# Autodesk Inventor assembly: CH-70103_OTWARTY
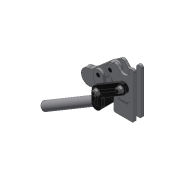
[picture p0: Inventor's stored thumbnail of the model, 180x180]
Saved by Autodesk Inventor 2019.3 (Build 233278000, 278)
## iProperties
Company: Î¢ÈíÖÐ¹ú
Created: 2012-10
Part Number: CH-70103_OTWARTY
Material: Ogólny
Description: STEP AP203
Document SubType Name: Assembly
Designer: CADENGINEERING4
Stock Number: DOCISKI CIĘŻKIE
Sending System: SolidWorks 2010
Preprocessor: SwSTEP 2.0
Title: CH-70103.STEP
Author: Î¢ÈíÓÃ»§
Revision Number: ÈÎºÎ
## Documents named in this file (11)
- D:\Vault_2016\Projekty\NASZ KATALOG\CLAMPTEK\STRONA\Heavy duty weldables\CH-70103\CH-70103_OTWARTY.iam
- D:\Vault_2016\Projekty\NASZ KATALOG\CLAMPTEK\STRONA\Heavy duty weldables\CH-70103\3-8-16 LOCK NUT.ipt
- D:\Vault_2016\Projekty\NASZ KATALOG\CLAMPTEK\STRONA\Heavy duty weldables\CH-70103\70103-10.ipt
- D:\Vault_2016\Projekty\NASZ KATALOG\CLAMPTEK\STRONA\Heavy duty weldables\CH-70103\70103-06.ipt
- D:\Vault_2016\Projekty\NASZ KATALOG\CLAMPTEK\STRONA\Heavy duty weldables\CH-70103\70103-04.ipt
- D:\Vault_2016\Projekty\NASZ KATALOG\CLAMPTEK\STRONA\Heavy duty weldables\CH-70103\70103-08.ipt
- D:\Vault_2016\Projekty\NASZ KATALOG\CLAMPTEK\STRONA\Heavy duty weldables\CH-70103\70103-02.ipt
- D:\Vault_2016\Projekty\NASZ KATALOG\CLAMPTEK\STRONA\Heavy duty weldables\CH-70103\70103-01.ipt
- D:\Vault_2016\Projekty\NASZ KATALOG\CLAMPTEK\STRONA\Heavy duty weldables\CH-70103\70103-03.ipt
- D:\Vault_2016\Projekty\NASZ KATALOG\CLAMPTEK\STRONA\Heavy duty weldables\CH-70103\70103-07.ipt
- D:\Vault_2016\Projekty\NASZ KATALOG\CLAMPTEK\STRONA\Heavy duty weldables\CH-70103\70103-05.ipt
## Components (17 placed, 10 different names)
1. 70103-01_8 — Zestawiające:28
2. 3-8-16 LOCK NUT:3 — Zestawiające:24, Zestawiające:26
3. 70103-10:3 — Zestawiające:5, Zestawiające:6, Zestawiające:7
4. 70103-06:3 — Zestawiające:10, Zestawiające:11, Równoległe:2
5. 70103-04:3 — Zestawiające:12, Równoległe:6, Zestawiające:29
6. 70103-08:3 — Zestawiające:17, Zestawiające:21, Zestawiające:22, Zestawiające:23
7. 70103-02:2 — Zestawiające:1, Zestawiające:2, Zestawiające:6, Zestawiające:19, Zestawiające:21, Zestawiające:22, Zestawiające:25
8. 3-8-16 LOCK NUT:4 — Zestawiające:4, Zestawiające:7
9. 70103-06:4 — Zestawiające:12, Zestawiające:13, Zestawiające:14, Równoległe:5
10. 70103-03:3 — Zestawiające:8, Zestawiające:15, Zestawiające:18, Zestawiające:19, Zestawiające:29
11. 70103-07:3 — Zestawiające:15, Zestawiające:16, Zestawiające:17, Zestawiające:18, Zestawiające:20
12. 70103-10:4 — Zestawiające:23, Zestawiające:24, Zestawiające:25, Zestawiające:26
13. 70103-07:4 — Zestawiające:3, Równoległe:1
14. 70103-05:2 — Równoległe:1, Zestawiające:8, Zestawiające:9, Zestawiające:11, Równoległe:2, Równoległe:3, Zestawiające:13, Równoległe:5
15. 70103-08:4 — Zestawiające:1, Zestawiające:2, Zestawiające:3, Zestawiające:4, Zestawiające:5
16. 70103-03:4 — Zestawiające:9, Zestawiające:14, Zestawiające:16, Zestawiające:20, Równoległe:6
17. 70103-04:4 — Zestawiające:10, Równoległe:3, Zestawiające:28
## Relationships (33: Mate 28, Flush 5)
- Zestawiające:1 [Mate]: 70103-02:2 ↔ 70103-08:4
- Zestawiające:2 [Mate]: 70103-02:2 ↔ 70103-08:4
- Zestawiające:3 [Mate]: 70103-07:4 ↔ 70103-08:4
- Zestawiające:4 [Mate]: 3-8-16 LOCK NUT:4 ↔ 70103-08:4
- Zestawiające:5 [Mate]: 70103-10:3 ↔ 70103-08:4
- Zestawiające:6 [Mate]: 70103-10:3 ↔ 70103-02:2
- Zestawiające:7 [Mate]: 70103-10:3 ↔ 3-8-16 LOCK NUT:4
- Równoległe:1 [Flush]: 70103-07:4 ↔ 70103-05:2
- Zestawiające:8 [Mate]: 70103-03:3 ↔ 70103-05:2
- Zestawiające:9 [Mate]: 70103-05:2 ↔ 70103-03:4
- Zestawiające:10 [Mate]: 70103-06:3 ↔ 70103-04:4
- Zestawiające:11 [Mate]: 70103-06:3 ↔ 70103-05:2
- Równoległe:2 [Flush]: 70103-06:3 ↔ 70103-05:2
- Równoległe:3 [Flush]: 70103-05:2 ↔ 70103-04:4
- Zestawiające:12 [Mate]: 70103-04:3 ↔ 70103-06:4
- Zestawiające:13 [Mate]: 70103-06:4 ↔ 70103-05:2
- Zestawiające:14 [Mate]: 70103-06:4 ↔ 70103-03:4
- Zestawiające:15 [Mate]: 70103-03:3 ↔ 70103-07:3
- Zestawiające:16 [Mate]: 70103-07:3 ↔ 70103-03:4
- Zestawiające:17 [Mate]: 70103-08:3 ↔ 70103-07:3
- Zestawiające:18 [Mate]: 70103-03:3 ↔ 70103-07:3
- Zestawiające:19 [Mate]: 70103-02:2 ↔ 70103-03:3
- Zestawiające:20 [Mate]: 70103-07:3 ↔ 70103-03:4
- Zestawiające:21 [Mate]: 70103-08:3 ↔ 70103-02:2
- Zestawiające:22 [Mate]: 70103-08:3 ↔ 70103-02:2
- Zestawiające:23 [Mate]: 70103-08:3 ↔ 70103-10:4
- Zestawiające:24 [Mate]: 3-8-16 LOCK NUT:3 ↔ 70103-10:4
- Zestawiające:25 [Mate]: 70103-02:2 ↔ 70103-10:4
- Zestawiające:26 [Mate]: 3-8-16 LOCK NUT:3 ↔ 70103-10:4
- Zestawiające:28 [Mate]: 70103-01_8 ↔ 70103-04:4
- Równoległe:5 [Flush]: 70103-06:4 ↔ 70103-05:2
- Równoległe:6 [Flush]: 70103-04:3 ↔ 70103-03:4
- Zestawiające:29 [Mate]: 70103-04:3 ↔ 70103-03:3
